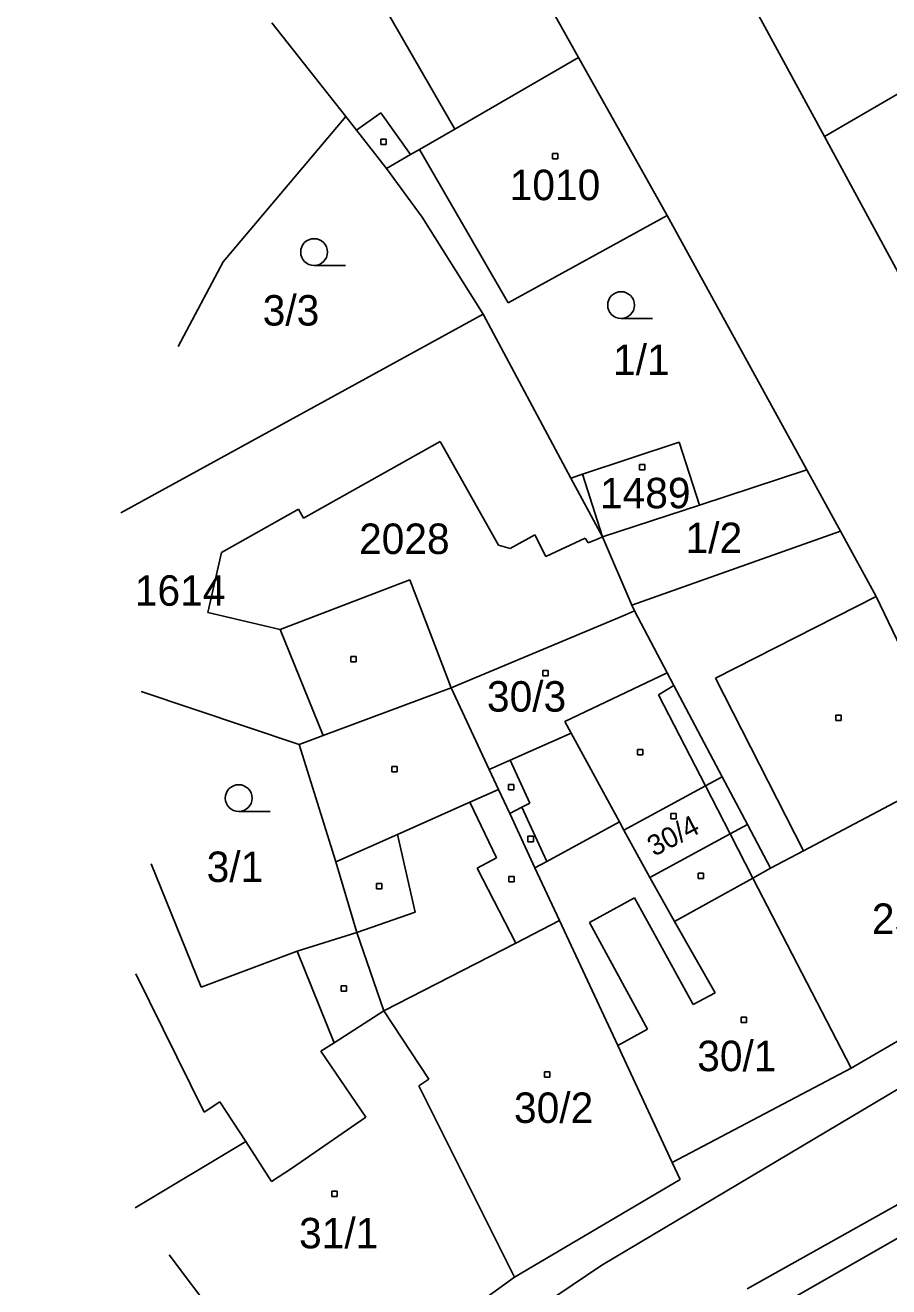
# Model space of a CAD drawing. Extents: x -711879 to -711361, y -1048782 to -1048177.
# Drawn here: x -711814.3 to -711766.1, y -1048613.1 to -1048542.7 of the extents above; entities that cross this region are included whole.
import ezdxf

# ---------------------------------------------------------------- set-up
doc = ezdxf.new("R2010")
doc.units = 0
for name, color, linetype in [('Vrstva 1', 7, 'Continuous'), ('Vrstva 14', 7, 'Continuous'), ('Vrstva 15', 7, 'Continuous'), ('Vrstva 2', 7, 'Continuous'), ('Vrstva 23', 7, 'Continuous'), ('Vrstva 25', 7, 'Continuous'), ('Vrstva 46', 7, 'Continuous')]:
    doc.layers.add(name, color=color, linetype=linetype)

msp = doc.modelspace()

# ---------------------------------------------------------------- linework, layer by layer
at = {"layer": 'Vrstva 1'}
for p, q in [((-711783.4, -1048544.52), (-711789.8, -1048533.1)), ((-711776.3, -1048536.72), (-711769.67, -1048548.94)), ((-711796.39, -1048547.82), (-711800.52, -1048542.59)), ((-711760.67, -1048543.7), (-711769.67, -1048548.94)), ((-711783.4, -1048544.52), (-711790.3, -1048548.52)), ((-711783.4, -1048544.52), (-711778.45, -1048553.35)), ((-711803.24, -1048555.93), (-711796.39, -1048547.82)), ((-711795.8, -1048548.58), (-711796.39, -1048547.82)), ((-711794.11, -1048550.72), (-711795.8, -1048548.58)), ((-711790.3, -1048548.52), (-711792.27, -1048549.66)), ((-711769.67, -1048548.94), (-711765.31, -1048556.97)), ((-711792.77, -1048549.95), (-711794.11, -1048550.72)), ((-711792.27, -1048549.66), (-711792.77, -1048549.95)), ((-711792.27, -1048549.66), (-711787.32, -1048558.22)), ((-711794.11, -1048550.72), (-711792.12, -1048553.43)), ((-711792.12, -1048553.43), (-711788.72, -1048558.85)), ((-711787.32, -1048558.22), (-711778.45, -1048553.35)), ((-711770.65, -1048567.55), (-711778.45, -1048553.35)), ((-711805.76, -1048560.66), (-711803.24, -1048555.93)), ((-711788.72, -1048558.85), (-711808.95, -1048569.95)), ((-711783.83, -1048568), (-711788.72, -1048558.85)), ((-711791.12, -1048565.97), (-711798.75, -1048570.25)), ((-711787.87, -1048571.75), (-711791.12, -1048565.97)), ((-711783.17, -1048567.78), (-711777.77, -1048565.99)), ((-711777.77, -1048565.99), (-711776.64, -1048569.51)), ((-711783.83, -1048568), (-711783.17, -1048567.78)), ((-711776.64, -1048569.51), (-711770.65, -1048567.55)), ((-711768.77, -1048570.97), (-711770.65, -1048567.55)), ((-711783.83, -1048568), (-711782.06, -1048571.28)), ((-711799.04, -1048569.74), (-711803.33, -1048572.15)), ((-711798.75, -1048570.25), (-711799.04, -1048569.74)), ((-711776.64, -1048569.51), (-711782.06, -1048571.28)), ((-711785.84, -1048571.17), (-711787.22, -1048571.94)), ((-711785.23, -1048572.38), (-711785.84, -1048571.17)), ((-711783.02, -1048571.35), (-711785.23, -1048572.38)), ((-711782.85, -1048571.61), (-711783.02, -1048571.35)), ((-711782.3, -1048571.4), (-711782.85, -1048571.61)), ((-711782.3, -1048571.4), (-711782.06, -1048571.28)), ((-711782.06, -1048571.28), (-711780.42, -1048575.1)), ((-711768.77, -1048570.97), (-711780.42, -1048575.1)), ((-711766.77, -1048574.61), (-711768.77, -1048570.97)), ((-711787.22, -1048571.94), (-711787.87, -1048571.75)), ((-711803.33, -1048572.15), (-711804.1, -1048575.5)), ((-711800.06, -1048576.46), (-711792.82, -1048573.68)), ((-711792.82, -1048573.68), (-711790.5, -1048579.72)), ((-711762.18, -1048584.23), (-711766.77, -1048574.61)), ((-711804.1, -1048575.5), (-711800.06, -1048576.46)), ((-711780.77, -1048575.64), (-711780.28, -1048575.42)), ((-711780.42, -1048575.1), (-711780.28, -1048575.42)), ((-711780.28, -1048575.42), (-711778.45, -1048578.88)), ((-711790.5, -1048579.72), (-711780.77, -1048575.64)), ((-711778.45, -1048578.88), (-711778.07, -1048579.59)), ((-711797.66, -1048582.38), (-711790.5, -1048579.72)), ((-711788.38, -1048584.27), (-711790.5, -1048579.72)), ((-711778.07, -1048579.59), (-711775.37, -1048584.68)), ((-711798.99, -1048582.88), (-711807.82, -1048579.92)), ((-711798.99, -1048582.88), (-711797.66, -1048582.38)), ((-711798.99, -1048582.88), (-711796.94, -1048589.42)), ((-711787.86, -1048585.38), (-711788.38, -1048584.27)), ((-711776.31, -1048585.19), (-711775.37, -1048584.68)), ((-711775.37, -1048584.68), (-711773.96, -1048587.35)), ((-711787.24, -1048586.73), (-711787.86, -1048585.38)), ((-711780.87, -1048587.65), (-711776.31, -1048585.19)), ((-711785.83, -1048589.76), (-711787.24, -1048586.73)), ((-711781.11, -1048587.2), (-711785.16, -1048589.4)), ((-711781.11, -1048587.2), (-711780.87, -1048587.65)), ((-711773.96, -1048587.35), (-711772.67, -1048589.78)), ((-711780.87, -1048587.65), (-711779.42, -1048590.3)), ((-711804.46, -1048596.43), (-711807.25, -1048589.54)), ((-711796.94, -1048589.42), (-711795.78, -1048593.37)), ((-711785.16, -1048589.4), (-711785.83, -1048589.76)), ((-711784.46, -1048592.7), (-711785.83, -1048589.76)), ((-711778.04, -1048592.75), (-711779.42, -1048590.3)), ((-711778.04, -1048592.75), (-711773.66, -1048590.33)), ((-711773.66, -1048590.33), (-711772.67, -1048589.78)), ((-711773.66, -1048590.33), (-711768.17, -1048600.95)), ((-711781.21, -1048599.68), (-711784.46, -1048592.7)), ((-711795.78, -1048593.37), (-711799.11, -1048594.42)), ((-711795.78, -1048593.37), (-711794.26, -1048597.75)), ((-711799.11, -1048594.42), (-711804.46, -1048596.43)), ((-711768.17, -1048600.95), (-711758.17, -1048595.09)), ((-711791.76, -1048601.56), (-711794.26, -1048597.75)), ((-711778.17, -1048606.2), (-711781.21, -1048599.68)), ((-711768.17, -1048600.95), (-711778.17, -1048606.2)), ((-711792.31, -1048601.93), (-711791.76, -1048601.56)), ((-711786.97, -1048612.61), (-711792.31, -1048601.93)), ((-711777.73, -1048607.15), (-711778.17, -1048606.2)), ((-711773.03, -1048614.7), (-711758.74, -1048606.51)), ((-711786.97, -1048612.61), (-711777.73, -1048607.15)), ((-711806.26, -1048611.37), (-711799.65, -1048620.09)), ((-711792.69, -1048616.72), (-711786.97, -1048612.61))]:
    msp.add_line(p, q, dxfattribs=at)
at = {"layer": 'Vrstva 2'}
for p, q in [((-711790.3, -1048548.52), (-711796.96, -1048536.97)), ((-711795.8, -1048548.58), (-711794.44, -1048547.61)), ((-711794.44, -1048547.61), (-711792.77, -1048549.95)), ((-711782.06, -1048571.28), (-711783.17, -1048567.78)), ((-711766.77, -1048574.61), (-711775.75, -1048579.18)), ((-711800.06, -1048576.46), (-711797.66, -1048582.38)), ((-711784.16, -1048581.6), (-711778.45, -1048578.88)), ((-711778.94, -1048580.1), (-711778.07, -1048579.59)), ((-711775.75, -1048579.18), (-711770.83, -1048588.81)), ((-711776.31, -1048585.19), (-711778.94, -1048580.1)), ((-711783.81, -1048582.24), (-711784.16, -1048581.6)), ((-711783.81, -1048582.24), (-711787.21, -1048583.75)), ((-711781.11, -1048587.2), (-711783.81, -1048582.24)), ((-711787.21, -1048583.75), (-711788.38, -1048584.27)), ((-711787.21, -1048583.75), (-711786.12, -1048586.15)), ((-711762.18, -1048584.23), (-711770.83, -1048588.81)), ((-711789.47, -1048586.1), (-711787.86, -1048585.38)), ((-711774.93, -1048587.87), (-711776.31, -1048585.19)), ((-711793.5, -1048587.89), (-711789.47, -1048586.1)), ((-711787.97, -1048589.21), (-711789.47, -1048586.1)), ((-711786.12, -1048586.15), (-711786.57, -1048586.38)), ((-711786.57, -1048586.38), (-711787.24, -1048586.73)), ((-711786.57, -1048586.38), (-711785.16, -1048589.4)), ((-711774.93, -1048587.87), (-711773.96, -1048587.35)), ((-711796.94, -1048589.42), (-711793.5, -1048587.89)), ((-711792.51, -1048592.23), (-711793.5, -1048587.89)), ((-711779.42, -1048590.3), (-711774.93, -1048587.87)), ((-711774.93, -1048587.87), (-711773.66, -1048590.33)), ((-711770.83, -1048588.81), (-711772.67, -1048589.78)), ((-711789.06, -1048589.78), (-711787.97, -1048589.21)), ((-711786.9, -1048593.96), (-711789.06, -1048589.78)), ((-711780.28, -1048591.44), (-711782.78, -1048592.82)), ((-711780.28, -1048591.44), (-711776.99, -1048597.39)), ((-711792.51, -1048592.23), (-711795.78, -1048593.37)), ((-711786.9, -1048593.96), (-711784.46, -1048592.7)), ((-711782.78, -1048592.82), (-711779.54, -1048598.77)), ((-711778.04, -1048592.75), (-711775.77, -1048596.74)), ((-711799.11, -1048594.42), (-711797.05, -1048599.53)), ((-711794.26, -1048597.75), (-711786.9, -1048593.96)), ((-711804.3, -1048603.4), (-711808.11, -1048595.68)), ((-711776.99, -1048597.39), (-711775.77, -1048596.74)), ((-711794.26, -1048597.75), (-711797.05, -1048599.53)), ((-711781.21, -1048599.68), (-711779.54, -1048598.77)), ((-711797.05, -1048599.53), (-711797.79, -1048600)), ((-711797.79, -1048600), (-711795.27, -1048603.68)), ((-711782.1, -1048611.94), (-711765.38, -1048602.01)), ((-711803.42, -1048602.83), (-711804.3, -1048603.4)), ((-711801.97, -1048605.03), (-711803.42, -1048602.83)), ((-711795.27, -1048603.68), (-711799.43, -1048606.54)), ((-711801.97, -1048605.03), (-711808.15, -1048608.73)), ((-711801.97, -1048605.03), (-711800.54, -1048607.26)), ((-711759.6, -1048605.21), (-711773.98, -1048613.26)), ((-711799.43, -1048606.54), (-711800.54, -1048607.26)), ((-711814.29, -1048633.54), (-711782.1, -1048611.94))]:
    msp.add_line(p, q, dxfattribs=at)
at = {"layer": 'Vrstva 23'}
for p, q in [((-711798.16, -1048556.14), (-711796.41, -1048556.14)), ((-711781.02, -1048559.1), (-711779.27, -1048559.1)), ((-711802.37, -1048586.62), (-711800.62, -1048586.62))]:
    msp.add_line(p, q, dxfattribs=at)
for centre in [(-711798.16, -1048555.39), (-711781.02, -1048558.35), (-711802.37, -1048585.87)]:
    msp.add_circle(centre, 0.75, dxfattribs=at)
at = {"layer": 'Vrstva 25'}
for p, q in [((-711794.43, -1048549.09), (-711794.13, -1048549.09)), ((-711794.43, -1048549.39), (-711794.43, -1048549.09)), ((-711794.13, -1048549.39), (-711794.43, -1048549.39)), ((-711794.13, -1048549.09), (-711794.13, -1048549.39)), ((-711784.85, -1048549.88), (-711784.55, -1048549.88)), ((-711784.85, -1048550.18), (-711784.85, -1048549.88)), ((-711784.55, -1048550.18), (-711784.85, -1048550.18)), ((-711784.55, -1048549.88), (-711784.55, -1048550.18)), ((-711780, -1048567.25), (-711779.7, -1048567.25)), ((-711780, -1048567.55), (-711780, -1048567.25)), ((-711779.7, -1048567.55), (-711780, -1048567.55)), ((-711779.7, -1048567.25), (-711779.7, -1048567.55)), ((-711796.11, -1048577.96), (-711795.81, -1048577.96)), ((-711796.11, -1048578.26), (-711796.11, -1048577.96)), ((-711795.81, -1048578.26), (-711796.11, -1048578.26)), ((-711795.81, -1048577.96), (-711795.81, -1048578.26)), ((-711785.39, -1048578.74), (-711785.09, -1048578.74)), ((-711785.39, -1048579.04), (-711785.39, -1048578.74)), ((-711785.09, -1048579.04), (-711785.39, -1048579.04)), ((-711785.09, -1048578.74), (-711785.09, -1048579.04)), ((-711769.03, -1048581.24), (-711768.73, -1048581.24)), ((-711769.03, -1048581.54), (-711769.03, -1048581.24)), ((-711768.73, -1048581.24), (-711768.73, -1048581.54)), ((-711768.73, -1048581.54), (-711769.03, -1048581.54)), ((-711780.1, -1048583.15), (-711779.8, -1048583.15)), ((-711780.1, -1048583.45), (-711780.1, -1048583.15)), ((-711779.8, -1048583.15), (-711779.8, -1048583.45)), ((-711779.8, -1048583.45), (-711780.1, -1048583.45)), ((-711793.83, -1048584.1), (-711793.53, -1048584.1)), ((-711793.83, -1048584.4), (-711793.83, -1048584.1)), ((-711793.53, -1048584.4), (-711793.83, -1048584.4)), ((-711793.53, -1048584.1), (-711793.53, -1048584.4)), ((-711787.3, -1048585.11), (-711787, -1048585.11)), ((-711787.3, -1048585.41), (-711787.3, -1048585.11)), ((-711787, -1048585.41), (-711787.3, -1048585.41)), ((-711787, -1048585.11), (-711787, -1048585.41)), ((-711778.24, -1048586.73), (-711777.94, -1048586.73)), ((-711778.24, -1048587.03), (-711778.24, -1048586.73)), ((-711777.94, -1048586.73), (-711777.94, -1048587.03)), ((-711777.94, -1048587.03), (-711778.24, -1048587.03)), ((-711786.22, -1048588), (-711785.92, -1048588)), ((-711786.22, -1048588.3), (-711786.22, -1048588)), ((-711785.92, -1048588.3), (-711786.22, -1048588.3)), ((-711785.92, -1048588), (-711785.92, -1048588.3)), ((-711787.29, -1048590.25), (-711786.99, -1048590.25)), ((-711787.29, -1048590.55), (-711787.29, -1048590.25)), ((-711786.99, -1048590.25), (-711786.99, -1048590.55)), ((-711776.72, -1048590.06), (-711776.42, -1048590.06)), ((-711776.72, -1048590.36), (-711776.72, -1048590.06)), ((-711776.42, -1048590.36), (-711776.72, -1048590.36)), ((-711776.42, -1048590.06), (-711776.42, -1048590.36)), ((-711794.68, -1048590.64), (-711794.38, -1048590.64)), ((-711794.68, -1048590.94), (-711794.68, -1048590.64)), ((-711794.38, -1048590.94), (-711794.68, -1048590.94)), ((-711794.38, -1048590.64), (-711794.38, -1048590.94)), ((-711786.99, -1048590.55), (-711787.29, -1048590.55)), ((-711796.65, -1048596.35), (-711796.35, -1048596.35)), ((-711796.65, -1048596.65), (-711796.65, -1048596.35)), ((-711796.35, -1048596.65), (-711796.65, -1048596.65)), ((-711796.35, -1048596.35), (-711796.35, -1048596.65)), ((-711774.32, -1048598.1), (-711774.02, -1048598.1)), ((-711774.32, -1048598.4), (-711774.32, -1048598.1)), ((-711774.02, -1048598.1), (-711774.02, -1048598.4)), ((-711774.02, -1048598.4), (-711774.32, -1048598.4)), ((-711785.29, -1048601.14), (-711784.99, -1048601.14)), ((-711785.29, -1048601.44), (-711785.29, -1048601.14)), ((-711784.99, -1048601.44), (-711785.29, -1048601.44)), ((-711784.99, -1048601.14), (-711784.99, -1048601.44)), ((-711797.17, -1048607.81), (-711796.87, -1048607.81)), ((-711797.17, -1048608.11), (-711797.17, -1048607.81)), ((-711796.87, -1048607.81), (-711796.87, -1048608.11)), ((-711796.87, -1048608.11), (-711797.17, -1048608.11))]:
    msp.add_line(p, q, dxfattribs=at)
at = {"layer": 'Vrstva 46'}
for p, q in [((-711791.12, -1048565.97), (-711791.12, -1048565.97)), ((-711782.3, -1048571.4), (-711782.3, -1048571.4)), ((-711792.82, -1048573.68), (-711792.82, -1048573.68)), ((-711780.77, -1048575.64), (-711780.77, -1048575.64)), ((-711800.06, -1048576.46), (-711800.06, -1048576.46)), ((-711790.5, -1048579.72), (-711790.5, -1048579.72)), ((-711796.94, -1048589.42), (-711796.94, -1048589.42)), ((-711799.11, -1048594.42), (-711799.11, -1048594.42)), ((-711797.79, -1048600), (-711797.79, -1048600)), ((-711803.42, -1048602.83), (-711803.42, -1048602.83)), ((-711804.3, -1048603.4), (-711804.3, -1048603.4)), ((-711795.27, -1048603.68), (-711795.27, -1048603.68)), ((-711801.97, -1048605.03), (-711801.97, -1048605.03)), ((-711799.43, -1048606.54), (-711799.43, -1048606.54))]:
    msp.add_line(p, q, dxfattribs=at)

# ---------------------------------------------------------------- texts
at = {"layer": 'Vrstva 14'}
for s, p in [('3/3', (-711801.03, -1048559.49)), ('1/1', (-711781.47, -1048562.25)), ('2028', (-711795.65, -1048572.24)), ('1/2', (-711777.42, -1048572.19)), ('3/1', (-711804.16, -1048590.55))]:
    msp.add_text(s, height=1.7, dxfattribs=at).set_placement(p)
at = {"layer": 'Vrstva 15'}
for s, p in [('1010', (-711787.24, -1048552.49)), ('1489', (-711782.2, -1048569.69)), ('1614', (-711808.17, -1048575.13)), ('30/3', (-711788.51, -1048581.04)), ('255', (-711767.02, -1048593.45)), ('30/1', (-711776.77, -1048601.11)), ('30/2', (-711787, -1048604)), ('31/1', (-711799, -1048611))]:
    msp.add_text(s, height=1.7, dxfattribs=at).set_placement(p)
msp.add_text('30/4', height=1.14, rotation=27.51849, dxfattribs=at).set_placement((-711779.176, -1048589.147))

doc.saveas('drawing.dxf')
